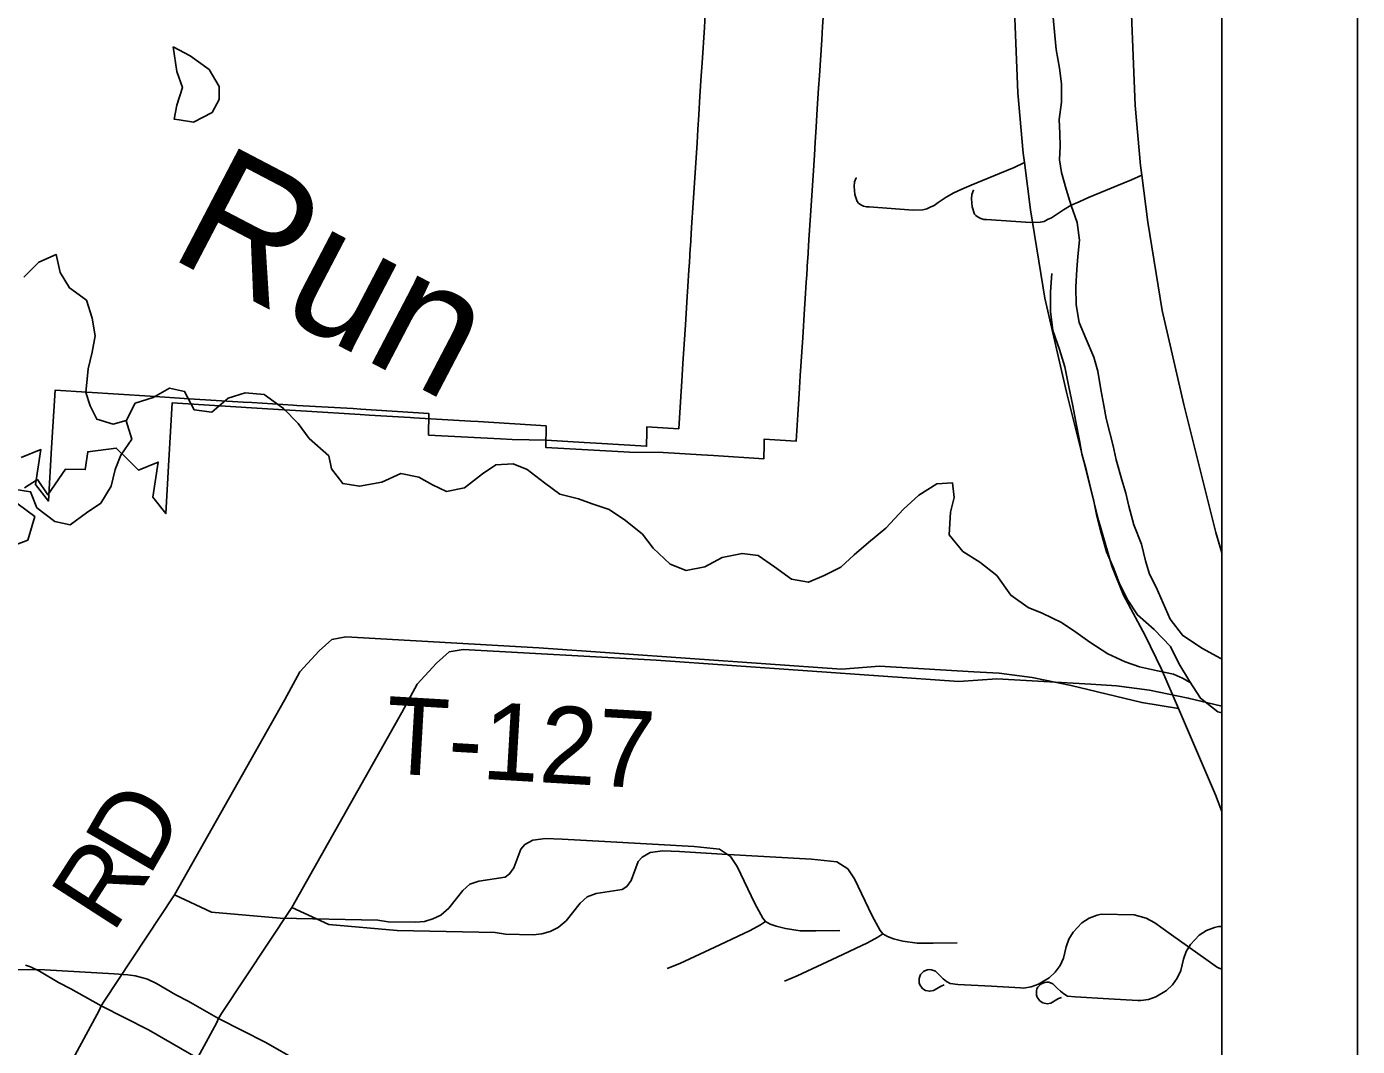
# Model space of a CAD drawing. Extents: x -38.2 to 41.9, y -4 to 24.9.
# Drawn here: x 8.019 to 9, y 16.76 to 17.512 of the extents above; entities that cross this region are included whole.
import ezdxf

# ---------------------------------------------------------------- set-up
doc = ezdxf.new("R2010")
doc.units = 0
for name, color, linetype in [('Default', 7, 'Continuous'), ('GM_X_County_Road', 7, 'Continuous'), ('GM_X_Interchange_Ramps', 7, 'Continuous'), ('GM_X_Major_River', 7, 'Continuous'), ('GM_X_Minor_Lake', 7, 'Continuous'), ('GM_X_Minor_River', 7, 'Continuous'), ('GM_X_Minor_River_Text', 7, 'Continuous'), ('GM_X_State_Location', 7, 'Continuous'), ('GM_X_State_Route', 7, 'Continuous'), ('GM_X_Township_Road', 7, 'Continuous'), ('GM_X_Township_Road_Text', 7, 'Continuous'), ('SH_Cut_Line', 7, 'Continuous'), ('SH_Data', 7, 'Continuous')]:
    doc.layers.add(name, color=color, linetype=linetype)

msp = doc.modelspace()

# ---------------------------------------------------------------- linework, layer by layer
at = {"layer": 'Default'}
msp.add_lwpolyline([(8.01509, 17.19395), (8.02953, 17.19979), (8.02568, 17.17402), (8.03517, 17.16183), (8.03746, 17.20122), (8.03994, 17.24349), (8.11008, 17.23912), (8.13887, 17.23733), (8.17852, 17.23486), (8.18513, 17.23445), (8.21538, 17.23257), (8.21808, 17.23242), (8.25979, 17.22999), (8.2654, 17.22966), (8.3154, 17.22644), (8.31538, 17.21054), (8.36829, 17.20764), (8.37698, 17.20716), (8.40189, 17.20681), (8.43008, 17.20509), (8.43886, 17.20455), (8.47603, 17.20226), (8.47617, 17.21282), (8.47622, 17.21667), (8.49973, 17.21521), (8.50099, 17.23494), (8.50197, 17.25012), (8.50281, 17.2633), (8.50463, 17.29171), (8.50598, 17.31274), (8.50644, 17.31999), (8.50723, 17.33234), (8.50758, 17.33778), (8.50826, 17.34834), (8.50834, 17.34952), (8.50923, 17.36353), (8.51037, 17.38157), (8.5106, 17.38526), (8.51225, 17.41106), (8.51321, 17.42599), (8.51383, 17.43563), (8.51452, 17.44658), (8.51539, 17.4602), (8.51636, 17.47528), (8.51697, 17.48477), (8.51865, 17.51091), (8.51928, 17.5207)], dxfattribs=at)
at = {"layer": 'GM_X_County_Road'}
for points in [[(8.01734, 17.17153), (8.027, 17.17768), (8.03469, 17.16647), (8.04766, 17.18536), (8.06225, 17.18505), (8.06409, 17.19827), (8.08513, 17.20098), (8.0924, 17.1938), (8.10157, 17.18476), (8.11601, 17.1906), (8.11215, 17.16483), (8.12165, 17.15264), (8.12394, 17.19203), (8.12641, 17.2343), (8.19656, 17.22993), (8.22535, 17.22814), (8.265, 17.22568), (8.2716, 17.22527), (8.30186, 17.22338), (8.30456, 17.22323), (8.34627, 17.2208), (8.35188, 17.22047), (8.40188, 17.21725), (8.40186, 17.20135), (8.45477, 17.19845), (8.46346, 17.19797), (8.48836, 17.19762), (8.51656, 17.1959), (8.52534, 17.19536), (8.56251, 17.19307), (8.56265, 17.20363), (8.56269, 17.20748), (8.5862, 17.20602), (8.58747, 17.22575), (8.58844, 17.24093), (8.58929, 17.25411), (8.59111, 17.28252), (8.59246, 17.30355), (8.59292, 17.3108), (8.59371, 17.32315), (8.59406, 17.32859), (8.59474, 17.33915), (8.59481, 17.34033), (8.59571, 17.35434), (8.59685, 17.37239), (8.59708, 17.37607), (8.59873, 17.40187), (8.59969, 17.4168), (8.60031, 17.42644), (8.601, 17.43739), (8.60187, 17.45101), (8.60284, 17.46609), (8.60345, 17.47558), (8.60513, 17.50172), (8.60575, 17.51151), (8.60682, 17.52819)], [(8.00627, 17.12788), (8.01981, 17.13313), (8.02518, 17.15047), (8.00615, 17.16443)]]:
    msp.add_lwpolyline(points, dxfattribs=at)
at = {"layer": 'GM_X_Interchange_Ramps'}
for points in [[(5.68741, 16.39544), (5.98531, 16.37641), (6.41299, 16.36022), (6.42632, 16.3595), (7.13357, 16.31975), (7.34417, 16.31068), (7.5793, 16.29614), (7.69014, 16.28944), (7.96963, 16.27524), (8.9, 16.22718), (8.9, 17.70631), (8.9, 17.90934), (8.9, 20.9), (5.12429, 20.9)], [(5.77389, 16.38625), (6.07178, 16.36722), (6.49947, 16.35103), (6.5128, 16.35031), (7.22005, 16.31056), (7.43065, 16.30149), (7.66578, 16.28695), (7.77662, 16.28025), (8.0561, 16.26605), (8.9, 16.22246), (8.9, 20.9), (5.21137, 20.9)], [(8.9, 17.12382), (8.89573, 17.1386), (8.87215, 17.23303), (8.85618, 17.30225), (8.84558, 17.36733), (8.84111, 17.40212), (8.84013, 17.40907), (8.83609, 17.45351), (8.83207, 17.55739)]]:
    msp.add_lwpolyline(points, dxfattribs=at)
at = {"layer": 'GM_X_Major_River'}
for points in [[(8.9, 17.04541), (8.89932, 17.04575), (8.88537, 17.05343), (8.87104, 17.06301), (8.86203, 17.07484), (8.8568, 17.08664), (8.85157, 17.09844), (8.84671, 17.10795), (8.84375, 17.11784), (8.84079, 17.13), (8.8352, 17.14446), (8.8315, 17.15815), (8.82929, 17.16765), (8.82632, 17.17753), (8.82225, 17.19236), (8.82004, 17.20262), (8.81745, 17.21212), (8.81486, 17.22276), (8.81303, 17.23226), (8.81083, 17.24404), (8.80865, 17.25771), (8.80568, 17.26798), (8.80008, 17.2813), (8.79486, 17.29348), (8.79267, 17.30639), (8.79237, 17.31967), (8.79321, 17.33257), (8.79402, 17.34205), (8.79523, 17.35418), (8.79342, 17.36709), (8.78895, 17.37965), (8.78524, 17.39181), (8.78191, 17.40398), (8.78045, 17.41347), (8.78089, 17.42333), (8.78057, 17.43282), (8.78026, 17.44307), (8.78185, 17.45596), (8.78193, 17.46924), (8.78049, 17.48101), (8.77792, 17.49469), (8.77685, 17.50494), (8.7758, 17.51823)], [(8.77464, 17.32966), (8.7738, 17.316), (8.77371, 17.30159), (8.77552, 17.28754), (8.78035, 17.27346), (8.78444, 17.26091), (8.78737, 17.2461), (8.79032, 17.23204), (8.79215, 17.2214), (8.79508, 17.20658), (8.79691, 17.1967), (8.80024, 17.18416), (8.80283, 17.1739), (8.80578, 17.16173), (8.80799, 17.15072), (8.81057, 17.14007), (8.81502, 17.12449), (8.82025, 17.11269), (8.82434, 17.10166), (8.83032, 17.08948), (8.83782, 17.07804), (8.85025, 17.06733), (8.86229, 17.05473), (8.86826, 17.04216), (8.87613, 17.02921), (8.88438, 17.01663), (8.89719, 17.00668), (8.9, 17.00589)]]:
    msp.add_lwpolyline(points, dxfattribs=at)
at = {"layer": 'GM_X_Minor_Lake'}
for points in [[(8.12697, 17.49654), (8.12963, 17.47833), (8.1338, 17.46656), (8.12964, 17.45367), (8.12775, 17.44342), (8.13151, 17.44283)], [(8.13151, 17.44283), (8.14214, 17.44114), (8.15576, 17.44834), (8.16105, 17.45782), (8.16104, 17.46731), (8.15347, 17.47983), (8.13946, 17.49009), (8.12697, 17.49654)]]:
    msp.add_lwpolyline(points, dxfattribs=at)
at = {"layer": 'GM_X_Minor_River'}
for points in [[(8.09242, 17.22134), (8.08283, 17.21844), (8.07072, 17.22224), (8.06579, 17.23211), (8.06276, 17.24198), (8.06426, 17.25943), (8.06729, 17.27157), (8.06955, 17.28371), (8.06728, 17.29662), (8.0631, 17.3099), (8.05061, 17.31901), (8.04379, 17.3304), (8.04076, 17.34368), (8.0279, 17.338), (8.01693, 17.327)], [(8.87676, 17.02825), (8.87108, 17.03126), (8.86443, 17.0344), (8.85269, 17.03668), (8.83945, 17.03973), (8.82885, 17.04352), (8.81598, 17.04922), (8.80273, 17.05795), (8.7925, 17.06517), (8.7819, 17.07238), (8.76752, 17.07922), (8.7573, 17.0834), (8.74443, 17.09251), (8.7342, 17.10693), (8.72171, 17.1168), (8.70922, 17.12478), (8.69899, 17.13692), (8.70012, 17.15362), (8.70276, 17.16462), (8.70162, 17.17525), (8.68989, 17.17449), (8.67665, 17.16615), (8.6653, 17.15591), (8.65244, 17.14188), (8.63957, 17.13126), (8.62898, 17.12216), (8.61915, 17.11305), (8.60704, 17.10699), (8.59531, 17.10206), (8.58282, 17.10434), (8.57032, 17.11346), (8.55821, 17.12181), (8.54648, 17.12333), (8.53172, 17.1203), (8.51886, 17.11348), (8.50523, 17.11083), (8.4935, 17.11539), (8.481, 17.12716), (8.47305, 17.13741), (8.46056, 17.14766), (8.44844, 17.15563), (8.43595, 17.15981), (8.42573, 17.16361), (8.41211, 17.16704), (8.40075, 17.17539), (8.38788, 17.18526), (8.37766, 17.18944), (8.36479, 17.18869), (8.35495, 17.18186), (8.34171, 17.17162), (8.32847, 17.16898), (8.31825, 17.17391), (8.30803, 17.17961), (8.29478, 17.18227), (8.28078, 17.17583), (8.26451, 17.17281), (8.25202, 17.17471), (8.24368, 17.18572), (8.24179, 17.19521), (8.2274, 17.20811), (8.21907, 17.21912), (8.20847, 17.23013), (8.19408, 17.24039), (8.18008, 17.24153), (8.16759, 17.23775), (8.15549, 17.22751), (8.14262, 17.22903), (8.13542, 17.2427), (8.12444, 17.24498), (8.11234, 17.23816), (8.09909, 17.23399), (8.09229, 17.22109), (8.09646, 17.20743), (8.08852, 17.19567), (8.08436, 17.18505), (8.08134, 17.17291), (8.07378, 17.16039), (8.06318, 17.15319), (8.05108, 17.14447), (8.03972, 17.14676), (8.02647, 17.15701), (8.02192, 17.16877), (8.01095, 17.1703)]]:
    msp.add_lwpolyline(points, dxfattribs=at)
at = {"layer": 'GM_X_State_Location'}
for points in [[(8.71698, 17.39086), (8.71709, 17.39089), (8.71587, 17.38784), (8.71542, 17.3845), (8.71603, 17.37872), (8.71781, 17.37341), (8.71879, 17.37224), (8.72056, 17.37107), (8.72232, 17.37009), (8.72467, 17.3695), (8.72663, 17.3695), (8.75913, 17.36716), (8.76618, 17.36736), (8.76912, 17.36794), (8.77166, 17.36931), (8.7744, 17.37049), (8.77734, 17.37264), (8.78341, 17.37656), (8.78889, 17.37989), (8.79496, 17.38244), (8.80182, 17.38557), (8.82277, 17.39419), (8.83353, 17.3985), (8.84111, 17.40212)], [(8.13633, 16.73551), (8.1589, 16.77721), (8.16042, 16.7806), (8.16277, 16.78415), (8.21458, 16.86249), (8.29557, 17.00608), (8.3069, 17.02688), (8.32107, 17.04237), (8.3305, 17.05078), (8.34089, 17.05255), (8.48298, 17.04456), (8.70616, 17.0289), (8.7341, 17.03092), (8.80363, 17.02687), (8.82252, 17.02576), (8.84666, 17.02265), (8.87537, 17.01668), (8.9, 17.01076)], [(8.21458, 16.86249), (8.24182, 16.8498), (8.29228, 16.84537), (8.36434, 16.84385), (8.37206, 16.8427), (8.39234, 16.84231), (8.3988, 16.84292), (8.40503, 16.84471), (8.41082, 16.84763), (8.41673, 16.85257), (8.42709, 16.86566), (8.43227, 16.87032), (8.43883, 16.87267), (8.45814, 16.87554), (8.46149, 16.87789), (8.46464, 16.88235), (8.46986, 16.89616), (8.47284, 16.89957), (8.47871, 16.90292), (8.48802, 16.90403), (8.5003, 16.90354), (8.53176, 16.90176), (8.59748, 16.89808), (8.61618, 16.8961), (8.62436, 16.89081), (8.62918, 16.88339), (8.64223, 16.85616), (8.64812, 16.84531), (8.65024, 16.84294), (8.6535, 16.8409), (8.65812, 16.8393), (8.66502, 16.83762), (8.67559, 16.83597), (8.68719, 16.83608), (8.70488, 16.83626)], [(8.7818, 16.7961), (8.77973, 16.79521), (8.7741, 16.79196), (8.77125, 16.79143), (8.76822, 16.79203), (8.76685, 16.79275), (8.76564, 16.79372), (8.7639, 16.79628), (8.76343, 16.79775), (8.76339, 16.80085), (8.76382, 16.80234), (8.76452, 16.80372), (8.76667, 16.80595), (8.76802, 16.80671), (8.7695, 16.80719), (8.77104, 16.80739), (8.77259, 16.80727), (8.77547, 16.80617), (8.77901, 16.80274), (8.78123, 16.80063), (8.78364, 16.79876), (8.78624, 16.79713), (8.79184, 16.79652), (8.81681, 16.79516), (8.83815, 16.79387), (8.84033, 16.79385), (8.84599, 16.79462), (8.85135, 16.79656), (8.85923, 16.80124), (8.8637, 16.80541), (8.86726, 16.81037), (8.86977, 16.81594), (8.8719, 16.82428), (8.87386, 16.82989), (8.8769, 16.83506), (8.88344, 16.8419), (8.88877, 16.8453), (8.89464, 16.84763), (8.89772, 16.84837), (8.9, 16.84832)], [(8.65024, 16.84294), (8.64646, 16.8404), (8.6388, 16.83629), (8.61657, 16.82578), (8.58702, 16.81191), (8.5777, 16.80818)], [(8.16042, 16.7806), (8.13807, 16.79326), (8.12895, 16.7979), (8.11486, 16.80636), (8.10823, 16.80955), (8.1047, 16.81063), (8.09895, 16.81198), (8.09356, 16.81282), (8.08356, 16.81342), (8.03241, 16.81647), (7.98159, 16.81677)], [(8.1972, 16.63877), (8.228, 16.63949), (8.23543, 16.64034), (8.24901, 16.6442), (8.2594, 16.65097), (8.26574, 16.65756), (8.26963, 16.66371), (8.2738, 16.67292), (8.27592, 16.68065), (8.27624, 16.69131), (8.27199, 16.70787), (8.26713, 16.71668), (8.26084, 16.72361), (8.25407, 16.72924), (8.19532, 16.76291), (8.16042, 16.7806)]]:
    msp.add_lwpolyline(points, dxfattribs=at)
at = {"layer": 'GM_X_State_Route'}
msp.add_lwpolyline([(8.9, 16.93316), (8.89531, 16.94539), (8.86824, 17.00899), (8.85569, 17.03799), (8.84354, 17.06286), (8.82757, 17.09247), (8.81905, 17.11389), (8.80925, 17.14778), (8.78567, 17.24222), (8.7697, 17.31143), (8.75911, 17.37652), (8.75463, 17.41131), (8.75366, 17.41826), (8.74961, 17.46269), (8.7456, 17.56658)], dxfattribs=at)
at = {"layer": 'GM_X_Township_Road'}
for points in [[(8.6305, 17.40005), (8.63061, 17.40008), (8.6294, 17.39703), (8.62894, 17.39369), (8.62955, 17.3879), (8.63134, 17.3826), (8.63232, 17.38143), (8.63408, 17.38025), (8.63584, 17.37928), (8.63819, 17.37869), (8.64015, 17.37869), (8.67265, 17.37635), (8.6797, 17.37654), (8.68264, 17.37713), (8.68519, 17.3785), (8.68793, 17.37968), (8.69086, 17.38183), (8.69693, 17.38575), (8.70242, 17.38908), (8.70848, 17.39163), (8.71534, 17.39476), (8.73629, 17.40338), (8.74706, 17.40769), (8.75463, 17.41131)], [(8.04985, 16.7447), (8.07242, 16.7864), (8.07395, 16.78979), (8.07629, 16.79334), (8.1281, 16.87168), (8.20909, 17.01526), (8.22043, 17.03607), (8.23459, 17.05156), (8.24403, 17.05997), (8.25441, 17.06174), (8.3965, 17.05375), (8.61968, 17.03809), (8.64762, 17.04011), (8.71715, 17.03606), (8.73605, 17.03495), (8.76019, 17.03184), (8.78889, 17.02587), (8.841, 17.01334), (8.86824, 17.00899)], [(8.1281, 16.87168), (8.15534, 16.85899), (8.2058, 16.85456), (8.27786, 16.85304), (8.28558, 16.85189), (8.30587, 16.8515), (8.31232, 16.85211), (8.31855, 16.8539), (8.32434, 16.85682), (8.33025, 16.86176), (8.34061, 16.87485), (8.34579, 16.87951), (8.35235, 16.88186), (8.37166, 16.88473), (8.37501, 16.88708), (8.37816, 16.89154), (8.38339, 16.90535), (8.38636, 16.90876), (8.39223, 16.91211), (8.40154, 16.91322), (8.41382, 16.91273), (8.44528, 16.91095), (8.511, 16.90726), (8.5297, 16.90529), (8.53788, 16.9), (8.54271, 16.89258), (8.55575, 16.86535), (8.56165, 16.8545), (8.56376, 16.85213), (8.56702, 16.85009), (8.57164, 16.84849), (8.57854, 16.84681), (8.58912, 16.84516), (8.60071, 16.84527), (8.6184, 16.84544)], [(8.69532, 16.80529), (8.69325, 16.8044), (8.68762, 16.80115), (8.68478, 16.80062), (8.68174, 16.80122), (8.68037, 16.80194), (8.67917, 16.80291), (8.67743, 16.80547), (8.67695, 16.80694), (8.67691, 16.81004), (8.67734, 16.81153), (8.67805, 16.81291), (8.68019, 16.81514), (8.68155, 16.8159), (8.68302, 16.81638), (8.68456, 16.81658), (8.68611, 16.81646), (8.689, 16.81536), (8.69253, 16.81193), (8.69476, 16.80982), (8.69717, 16.80794), (8.69976, 16.80632), (8.70536, 16.80571), (8.73034, 16.80435), (8.75167, 16.80306), (8.75385, 16.80304), (8.75951, 16.80381), (8.76487, 16.80575), (8.77275, 16.81043), (8.77722, 16.8146), (8.78078, 16.81956), (8.78329, 16.82513), (8.78542, 16.83346), (8.78738, 16.83908), (8.79042, 16.84425), (8.79697, 16.85109), (8.80229, 16.85449), (8.80816, 16.85682), (8.81124, 16.85755), (8.83535, 16.85707), (8.84436, 16.85445), (8.85067, 16.85101), (8.86307, 16.84215), (8.88831, 16.8242), (8.89684, 16.81822), (8.9, 16.81694)], [(8.56376, 16.85213), (8.55998, 16.84959), (8.55232, 16.84548), (8.53009, 16.83497), (8.50054, 16.8211), (8.49122, 16.81736)], [(8.07395, 16.78979), (8.05159, 16.80245), (8.04247, 16.80709), (8.02839, 16.81555), (8.02175, 16.81874), (8.01822, 16.81982)], [(8.11073, 16.64796), (8.14153, 16.64868), (8.14896, 16.64953), (8.16253, 16.65339), (8.17292, 16.66016), (8.17927, 16.66674), (8.18316, 16.6729), (8.18733, 16.68211), (8.18944, 16.68983), (8.18976, 16.7005), (8.18551, 16.71706), (8.18065, 16.72587), (8.17436, 16.7328), (8.16759, 16.73843), (8.10884, 16.7721), (8.07395, 16.78979)]]:
    msp.add_lwpolyline(points, dxfattribs=at)
at = {"layer": 'SH_Cut_Line'}
msp.add_lwpolyline([(5.68741, 16.39544), (5.98531, 16.37641), (6.41299, 16.36022), (6.42632, 16.3595), (7.13357, 16.31975), (7.34417, 16.31068), (7.5793, 16.29614), (7.69014, 16.28944), (7.96963, 16.27524), (8.9, 16.22718), (8.9, 17.70631), (8.9, 17.90934), (8.9, 20.9), (2.11034, 20.9)], dxfattribs=at)
at = {"layer": 'SH_Data'}
for p, q in [((9, 21), (9, 14)), ((8.9, 17.70631), (8.9, 14.1))]:
    msp.add_line(p, q, dxfattribs=at)

# ---------------------------------------------------------------- texts
at = {"layer": 'GM_X_Minor_River_Text'}
msp.add_text('Run', height=0.094698, rotation=332.40286, dxfattribs=at).set_placement((8.12234, 17.34253))
at = {"layer": 'GM_X_Township_Road_Text'}
for s, height, rotation, p in [('T-127', 0.056818, 356.66731, (8.2822, 16.96142)), ('D', 0.05682, 60.01286, (8.10911, 16.88411)), ('R', 0.05682, 57.2344, (8.08232, 16.84234))]:
    msp.add_text(s, height=height, rotation=rotation, dxfattribs=at).set_placement(p)

doc.saveas('drawing.dxf')
